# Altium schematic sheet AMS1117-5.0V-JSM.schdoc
size 127 x 101 mm
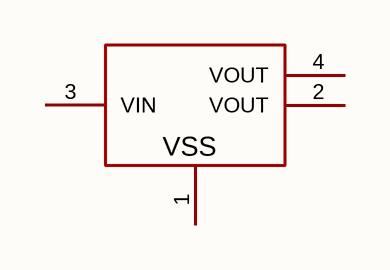
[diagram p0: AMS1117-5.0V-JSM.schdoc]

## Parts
U?  ams1117-5.0v-jsm  [SOT-223-4_L6.5-W3.5-P2.30-LS7.0-BR]  (value not drawn)

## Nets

Not connected (* = marked no-connect by the designer): U? 1(VSS) 2(VOUT) 3(VIN) 4(VOUT)

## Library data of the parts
U? = ams1117-5.0v-jsm: 输出极性:正极;工作电压:15V;输出电压:5V;输出电流:800mA;电源纹波抑制比(PSRR):-;输出类型:固定;; Manufacturer: JSMSEMI(杰盛微); AddInBom: yes; ModelId: 925194bf9823436183a3e0b978a8d076; ModelName: SOT-223-4P_L6.5-W3.5-H1.6-LS7.0-P2.30; ModelTransform: 279.89794,255.905,0,180,0,0,-0.0005,-0.0005,0; Output Configuration: 正极; Voltage - Supply: 15V; Output Voltage: 5V; Output Current: 800mA; Voltage Dropout: 1.3V@(800mA); standby current: 2mA; Output Type: 固定; Number of Outputs: 1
